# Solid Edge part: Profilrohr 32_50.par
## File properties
Username: ahadarics
Dokumentum tartalom típus: 0
Author: ahadarics
Last saved by: ahadarics
Revision: 79
Sűrűség: 0,000 kg/m^3
Pontosság: 0,990
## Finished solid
Body 1: solid body, 179 faces, 531 edges, 354 vertices.
  Faces by surface: cylinder 109, plane 70
  Edges by curve: line 313, circle 218
Bounding box of the edges (mm): 44.254 x 91.000 x 44.254, from (-22.1268, -58, -22.1268) to (22.1268, 33, 22.1268).
Cylindrical faces by radius (mm): R0.1 x16, R0.2 x30, R0.5 x32, R1 x6, R2.7 x8, R4.5 x4, R4.7 x4, R16 x1, R18 x8
Planar faces by outward normal: +x 4, +y 1, +z 6, -x 6, -y 1, -z 4, oblique 48
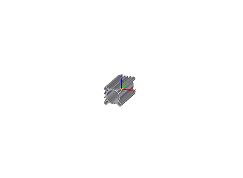
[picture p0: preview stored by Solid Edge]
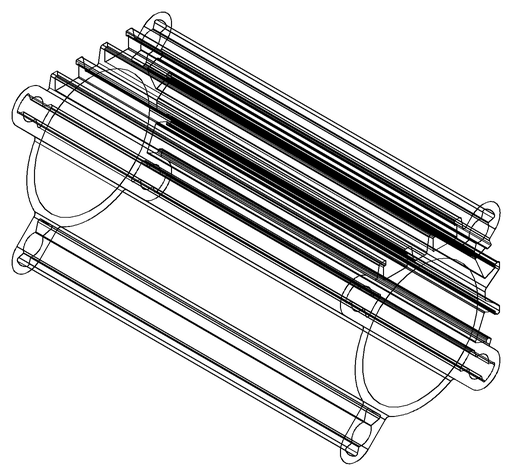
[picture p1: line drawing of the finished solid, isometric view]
